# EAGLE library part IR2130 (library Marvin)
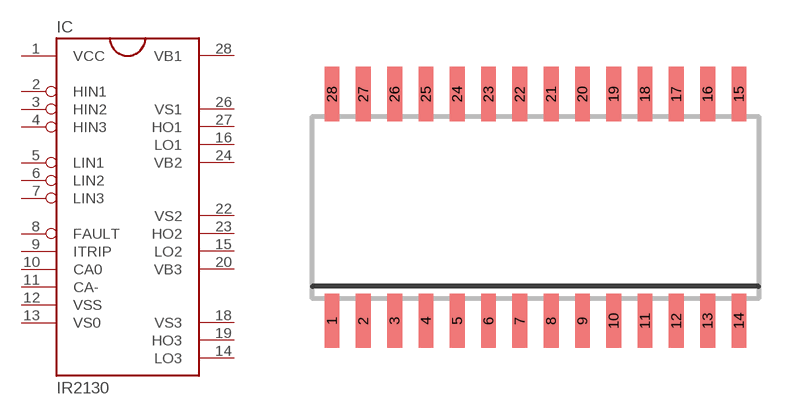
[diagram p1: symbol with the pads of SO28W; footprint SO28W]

Designator prefix IC

## IR2130S  [SO28W]
1  VCC
2  HIN1
3  HIN2
4  HIN3
5  LIN1
6  LIN2
7  LIN3
8  FAULT
9  ITRIP
10  CA0
11  CA-
12  VSS
13  VS0
14  LO3
15  LO2
16  LO1
18  VS3
19  HO3
20  VB3
22  VS2
23  HO2
24  VB2
26  VS1
27  HO1
28  VB1

## Footprint SO28W (pad centres in mm)
SMALL OUTLINE INTEGRATED CIRCUIT wide body 7.5 mm/JEDEC MO-119AB
smd 0.6 x 2.2: 1 -8.255,-4.6; 2 -6.985,-4.6; 3 -5.715,-4.6; 4 -4.445,-4.6; 5 -3.175,-4.6; 6 -1.905,-4.6; 7 -0.635,-4.6; 8 0.635,-4.6; 9 1.905,-4.6; 10 3.175,-4.6; 11 4.445,-4.6; 12 5.715,-4.6; 13 6.985,-4.6; 14 8.255,-4.6; 15 8.255,4.6; 16 6.985,4.6; 17 5.715,4.6; 18 4.445,4.6; 19 3.175,4.6; 20 1.905,4.6; 21 0.635,4.6; 22 -0.635,4.6; 23 -1.905,4.6; 24 -3.175,4.6; 25 -4.445,4.6; 26 -5.715,4.6; 27 -6.985,4.6; 28 -8.255,4.6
